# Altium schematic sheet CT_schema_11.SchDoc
size 387 x 385 mm
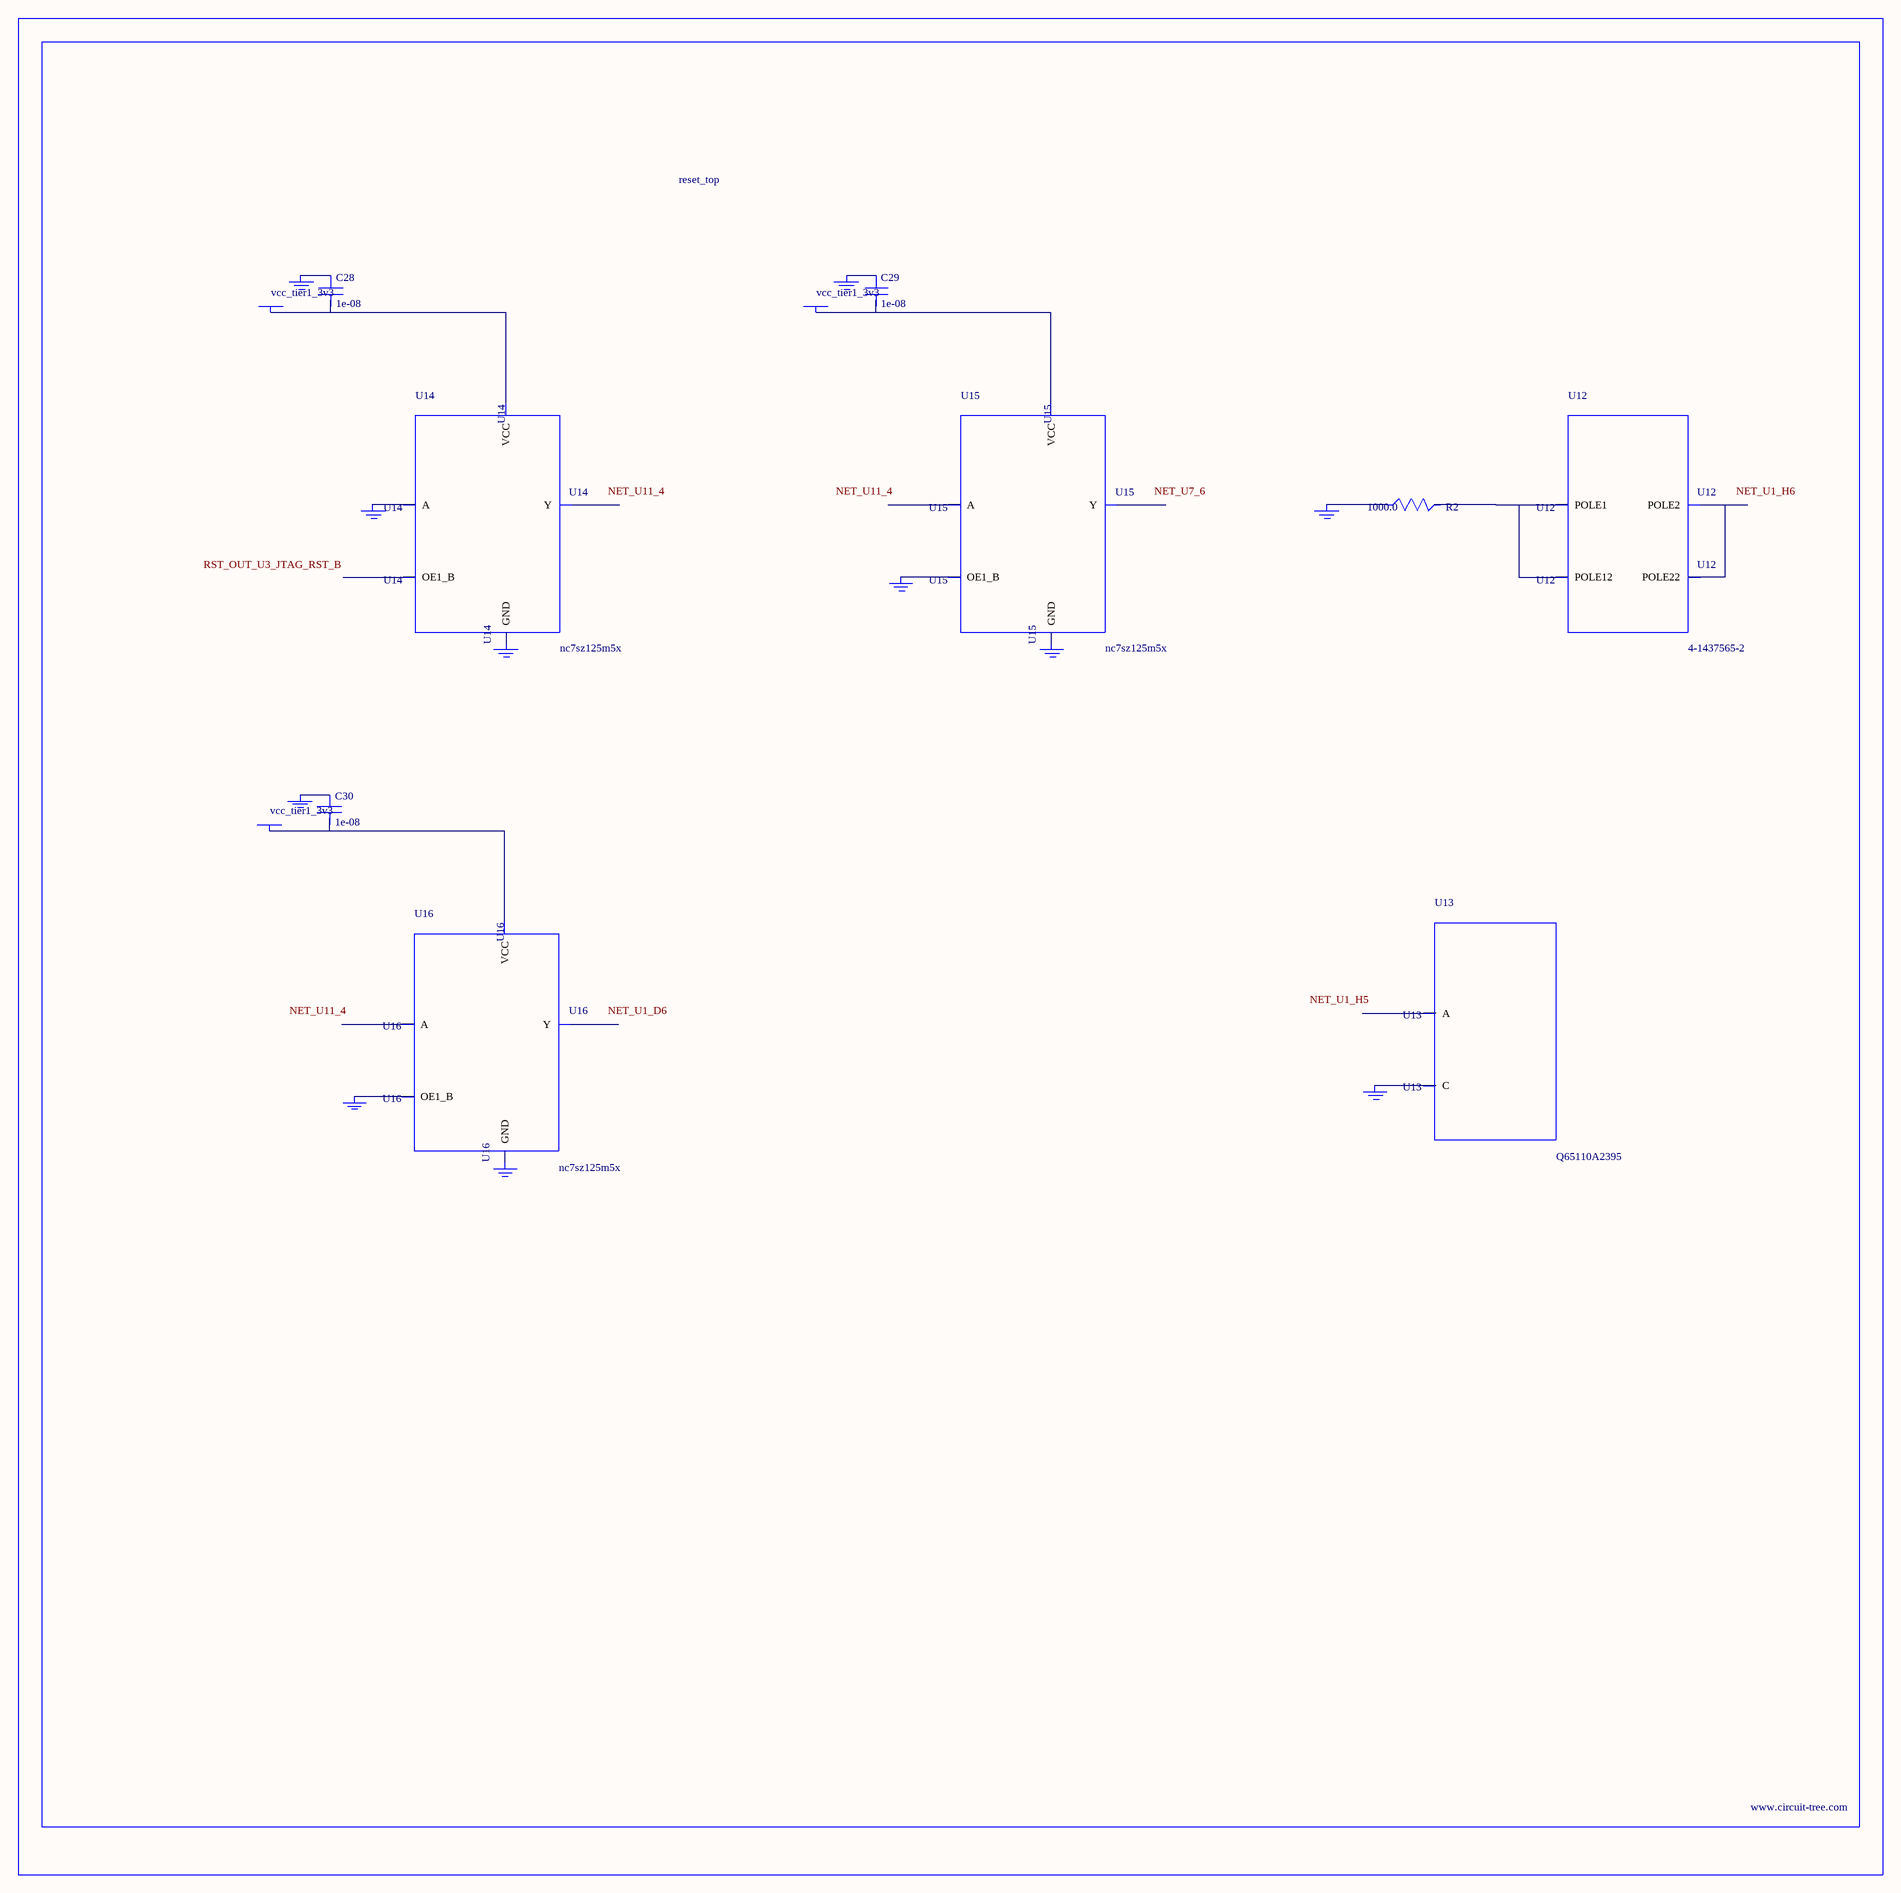
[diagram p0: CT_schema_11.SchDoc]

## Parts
BORDER10  (no value)
C28  1e-08  [C0402]
C29  1e-08  [C0402]
C30  1e-08  [C0402]
GND_INSTANCE_10_0  (no value)
GND_INSTANCE_10_1  (no value)
GND_INSTANCE_10_2  (no value)
GND_INSTANCE_10_3  (no value)
GND_INSTANCE_10_4  (no value)
GND_INSTANCE_10_5  (no value)
GND_INSTANCE_10_6  (no value)
GND_INSTANCE_10_7  (no value)
GND_INSTANCE_10_8  (no value)
GND_INSTANCE_10_9  (no value)
GND_INSTANCE_10_10  (no value)
POWER_INSTANCE_10_0  vcc_tier1_3v3
POWER_INSTANCE_10_1  vcc_tier1_3v3
POWER_INSTANCE_10_2  vcc_tier1_3v3
R2  1000.0  [R0603]
U12  4-1437565-2  [SW_4-1437565-2]
U13  Q65110A2395  [LGM67K-G1J2-24-Z]
U14  nc7sz125m5x  [NC7SZ125M5X]
U15  nc7sz125m5x  [NC7SZ125M5X]
U16  nc7sz125m5x  [NC7SZ125M5X]

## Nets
NetC28_1: C28.1 GND_INSTANCE_10_2.0(GND)
NetC28_2: C28.2 POWER_INSTANCE_10_0.0(PWR) U14.5(VCC)
NetC29_1: C29.1 GND_INSTANCE_10_5.0(GND)
NetC29_2: C29.2 POWER_INSTANCE_10_1.0(PWR) U15.5(VCC)
NetC30_1: C30.1 GND_INSTANCE_10_8.0(GND)
NetC30_2: C30.2 POWER_INSTANCE_10_2.0(PWR) U16.5(VCC)
NetGND_INSTANCE_10_0_0: GND_INSTANCE_10_0.0(GND) R2.1
NetGND_INSTANCE_10_1_0: GND_INSTANCE_10_1.0(GND) U13.C
NetGND_INSTANCE_10_3_0: GND_INSTANCE_10_3.0(GND) U14.2(A)
NetGND_INSTANCE_10_4_0: GND_INSTANCE_10_4.0(GND) U14.3(GND)
NetGND_INSTANCE_10_6_0: GND_INSTANCE_10_6.0(GND) U15.1(OE1_B)
NetGND_INSTANCE_10_7_0: GND_INSTANCE_10_7.0(GND) U15.3(GND)
NetGND_INSTANCE_10_9_0: GND_INSTANCE_10_9.0(GND) U16.1(OE1_B)
NetGND_INSTANCE_10_10_0: GND_INSTANCE_10_10.0(GND) U16.3(GND)
NetR2_2: R2.2 U12.1(POLE1) U12.2(POLE12)
NetU12_3: U12.3(POLE2) U12.4(POLE22)

Not connected (* = marked no-connect by the designer): U13 A; U14 1(OE1_B) 4(Y); U15 2(A) 4(Y); U16 2(A) 4(Y)

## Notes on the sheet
- Labels drawn without touching a wire or pin: NET_U1_D6, NET_U1_H5, NET_U1_H6, NET_U7_6, NET_U11_4, RST_OUT_U3_JTAG_RST_B

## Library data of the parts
BORDER10 = BORDER_PAGE10
C28-C30 = C0402C103K3RAC
GND_INSTANCE_10_0-GND_INSTANCE_10_10 = GND
POWER_INSTANCE_10_0-POWER_INSTANCE_10_2 = PWR
R2 = RC0603JR-071KL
